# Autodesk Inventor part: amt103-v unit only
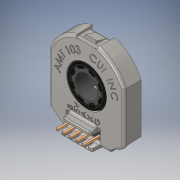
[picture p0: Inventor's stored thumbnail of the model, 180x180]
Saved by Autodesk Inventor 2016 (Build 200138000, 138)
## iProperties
Created: 2017-03
Part Number: amt103-v unit only
Material: Generic
Document SubType Name: Modeling
Designer: TDM
Density: 1 g/cm^3
Appearance: Default
Author: TDM
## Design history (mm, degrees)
derived "amt103-v unit only.iam"
body "Solid1"
node "amt103-v_24.ipt:1"
node "amt103-v_22.ipt:1"
node "amt103-v_21.ipt:1"
node "amt103-v_20.ipt:1"
node "amt103-v_19.ipt:1"
node "amt103-v_18.ipt:1"
node "amt103-v_17.ipt:1"
node "amt103-v_16.ipt:1"
node "amt103-v_15.ipt:1"
node "amt103-v_14.ipt:1"
node "amt103-v_13.ipt:1"
node "amt103-v_12.ipt:1"
node "amt103-v_11.ipt:1"
node "amt103-v_10.ipt:1"
node "amt103-v_09.ipt:1"
node "amt103-v_08.ipt:1"
node "amt103-v_07.ipt:1"
node "amt103-v_06.ipt:1"
node "amt103-v_05.ipt:1"
node "amt103-v_04.ipt:1"
node "amt103-v_03.ipt:1"
node "amt103-v_02.ipt:1"
node "amt103-v_01.ipt:1"
